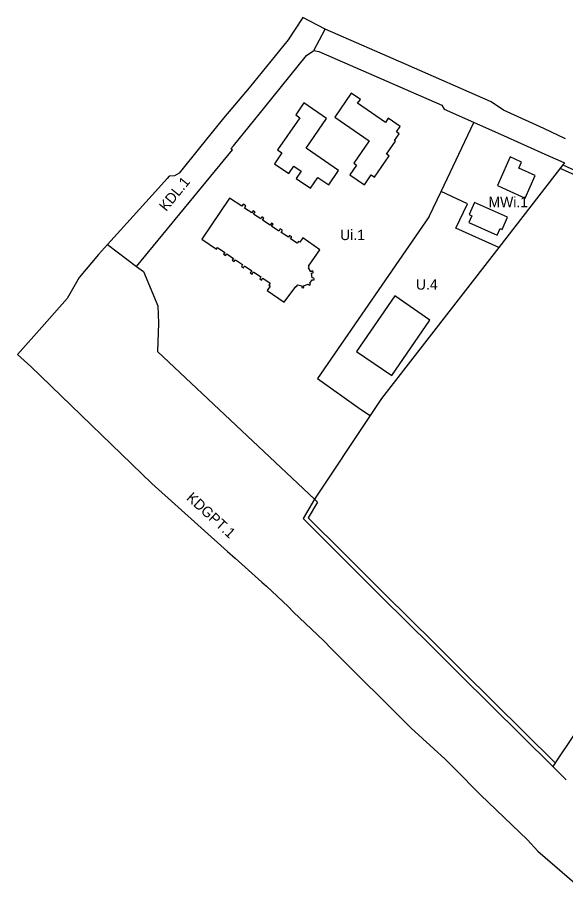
# Model space of a CAD drawing. Extents: x 7427219 to 7428976, y 5542673 to 5543767.
# Drawn here: x 7427399.8 to 7427662.8, y 5542853.3 to 5543277.1 of the extents above; entities that cross this region are included whole.
import ezdxf

# ---------------------------------------------------------------- set-up
doc = ezdxf.new("R2010")
doc.units = 0
for name, color, linetype in [('linie rozgraniczające', 7, 'Continuous'), ('nieprzekraczalne linie zabudowy', 7, 'Continuous'), ('obowiazujace linie zabudowy', 7, 'Continuous'), ('przeznaczenia terenów', 7, 'Continuous')]:
    doc.layers.add(name, color=color, linetype=linetype)

msp = doc.modelspace()

# ---------------------------------------------------------------- linework, layer by layer
at = {"layer": 'linie rozgraniczające'}
for p, q in [((7427615.83, 5543187.62), (7427603.18, 5543193.61)), ((7427597.49, 5543181.6), (7427543.77, 5543103.7))]:
    msp.add_line(p, q, dxfattribs=at)
for points in [[(7427547.42, 5543271.6), (7427536.8, 5543277.12), (7427529.68, 5543266.5), (7427511.02, 5543243.35), (7427498.71, 5543228.81), (7427487.19, 5543214.58), (7427477.35, 5543202.44), (7427475.19, 5543201.11), (7427472.52, 5543200.95), (7427471.58, 5543199.8), (7427467.37, 5543195.09), (7427446.18, 5543171.61), (7427442.97, 5543168.04)], [(7427542.01, 5543261.33), (7427547.42, 5543271.6)], [(7427662.95, 5543218.86), (7427652.55, 5543223.76), (7427633.2, 5543232.59), (7427627.2, 5543236.59), (7427586.32, 5543254.53), (7427547.42, 5543271.6)], [(7427456.96, 5543157.51), (7427503.06, 5543213.5), (7427502.24, 5543214.02), (7427503.46, 5543215.53), (7427518.51, 5543234.15), (7427538.52, 5543258.91), (7427542.01, 5543261.33)], [(7427542.01, 5543261.33), (7427544.42, 5543260.9), (7427603.44, 5543234.99), (7427604.62, 5543233.17), (7427631.67, 5543221.07)], [(7427597.49, 5543181.6), (7427603.18, 5543193.61), (7427618.89, 5543226.79)], [(7427631.67, 5543221.07), (7427654.47, 5543210.87), (7427659.22, 5543208.74), (7427662.41, 5543207.31), (7427661.57, 5543206.3)], [(7427661.57, 5543206.3), (7427630.91, 5543166.64)], [(7427661.57, 5543206.3), (7427676.7, 5543199.54), (7427691.82, 5543192.78), (7427705.68, 5543186.58), (7427719.54, 5543180.39), (7427732.45, 5543174.31), (7427745.35, 5543168.23)], [(7427630.91, 5543166.64), (7427610.27, 5543175.88), (7427615.83, 5543187.62)], [(7427442.97, 5543168.04), (7427438.63, 5543163.23), (7427429.35, 5543152.29), (7427423.66, 5543142.17), (7427411.39, 5543128.32), (7427399.81, 5543115.25), (7427406.08, 5543109.39), (7427464.3, 5543053.23), (7427500.6, 5543020.46), (7427504.23, 5543017.32), (7427517.14, 5543005.76), (7427519.34, 5543003.79), (7427529.74, 5542994.1), (7427532.3, 5542991.42), (7427540.99, 5542983.15), (7427546.83, 5542977.53), (7427550.71, 5542973.49), (7427588.86, 5542935.6), (7427605.09, 5542920.62), (7427609.64, 5542916.28), (7427622.1, 5542903.58), (7427644.62, 5542881.96), (7427649.66, 5542876.48), (7427676.46, 5542853.3)], [(7427442.97, 5543168.04), (7427456.96, 5543157.51)], [(7427630.91, 5543166.64), (7427574.59, 5543094.05), (7427569.09, 5543085.81), (7427542.29, 5543045.63)], [(7427456.96, 5543157.51), (7427460.18, 5543155.09), (7427467.08, 5543138.63), (7427467.4, 5543130.24), (7427467.03, 5543116.62), (7427542.29, 5543045.63)], [(7427543.77, 5543103.7), (7427564.53, 5543088.95), (7427569.09, 5543085.81)], [(7427542.29, 5543045.63), (7427536.85, 5543036.29), (7427554.82, 5543018.4), (7427574.7, 5542998.59), (7427598.52, 5542974.95), (7427612.07, 5542961.53), (7427656.8, 5542917.2)], [(7427729.71, 5543025.77), (7427700.38, 5542982.08), (7427659.59, 5542921.33), (7427656.8, 5542917.2)], [(7427656.8, 5542917.2), (7427663.24, 5542910.82)]]:
    msp.add_lwpolyline(points, dxfattribs=at)
at = {"layer": 'nieprzekraczalne linie zabudowy'}
for p, q in [((7427580.87, 5543143.42), (7427562.5, 5543116.7)), ((7427597.8, 5543131.78), (7427580.87, 5543143.42)), ((7427579.43, 5543105.06), (7427597.8, 5543131.78)), ((7427562.5, 5543116.7), (7427579.43, 5543105.06))]:
    msp.add_line(p, q, dxfattribs=at)
for points in [[(7427744.49, 5543166.43), (7427718.71, 5543178.57), (7427660.31, 5543204.67)], [(7427542.29, 5543045.63), (7427543.78, 5543044.22), (7427539.36, 5543036.62), (7427556.23, 5543019.82), (7427576.11, 5543000.01), (7427599.92, 5542976.37), (7427613.48, 5542962.95), (7427657.94, 5542918.89)]]:
    msp.add_lwpolyline(points, dxfattribs=at)
at = {"layer": 'obowiazujace linie zabudowy'}
for points in [[(7427566.3, 5543196.78), (7427569.54, 5543201.53), (7427571.19, 5543200.4), (7427578.25, 5543210.72), (7427577.01, 5543211.56), (7427581.21, 5543217.71), (7427580.8, 5543217.99), (7427583.09, 5543221.33), (7427581.81, 5543222.21), (7427583.56, 5543224.76), (7427577.77, 5543228.73), (7427576.44, 5543226.79), (7427563.08, 5543235.95), (7427564.38, 5543237.85), (7427560.03, 5543240.83), (7427552.11, 5543229.25), (7427568.65, 5543217.95), (7427561.26, 5543207.13), (7427562.54, 5543206.26), (7427559.32, 5543201.55)], [(7427540.42, 5543195.1), (7427544.01, 5543200.3), (7427549.17, 5543196.75), (7427553.95, 5543203.71), (7427538.38, 5543214.43), (7427548.17, 5543228.71), (7427537.27, 5543236.15), (7427533.33, 5543230.39), (7427535.38, 5543228.97), (7427524.63, 5543213.52), (7427526.72, 5543212.09), (7427523.16, 5543206.91), (7427530.09, 5543202.23), (7427532.4, 5543205.66), (7427535.93, 5543203.27), (7427533.59, 5543199.79)], [(7427545, 5543165.49), (7427536.7, 5543171.26), (7427535.27, 5543169.12), (7427534.65, 5543169.53), (7427534.1, 5543168.7), (7427530.85, 5543170.86), (7427531.45, 5543171.76), (7427530.43, 5543172.43), (7427529.84, 5543171.54), (7427526.28, 5543173.9), (7427526.98, 5543174.96), (7427525.94, 5543175.65), (7427525.22, 5543174.56), (7427521.79, 5543176.84), (7427522.45, 5543177.83), (7427521.71, 5543178.32), (7427521.04, 5543177.31), (7427517.37, 5543179.75), (7427518.02, 5543180.74), (7427517.1, 5543181.35), (7427516.52, 5543180.46), (7427513.14, 5543182.71), (7427513.81, 5543183.72), (7427512.92, 5543184.31), (7427512.22, 5543183.26), (7427508.69, 5543185.61), (7427509.34, 5543186.58), (7427508.03, 5543187.44), (7427507.41, 5543186.52), (7427501.62, 5543190.38), (7427488.27, 5543170.64), (7427495.23, 5543165.8), (7427495.77, 5543166.59), (7427499.25, 5543164.21), (7427498.67, 5543163.36), (7427499.61, 5543162.72), (7427500.21, 5543163.6), (7427503.45, 5543161.38), (7427502.85, 5543160.49), (7427503.76, 5543159.87), (7427504.38, 5543160.77), (7427507.86, 5543158.39), (7427507.25, 5543157.49), (7427508.19, 5543156.85), (7427508.82, 5543157.76), (7427512.19, 5543155.45), (7427511.51, 5543154.46), (7427512.42, 5543153.83), (7427513.14, 5543154.89), (7427516.67, 5543152.47), (7427516.04, 5543151.54), (7427516.98, 5543150.89), (7427517.62, 5543151.82), (7427521.06, 5543149.46), (7427520.41, 5543148.51), (7427521.03, 5543148.09), (7427519.59, 5543145.98), (7427527.81, 5543140.36), (7427533.34, 5543147.94), (7427533.77, 5543147.86), (7427534.32, 5543148.7), (7427536.29, 5543148.23), (7427536.35, 5543147.35), (7427536.84, 5543147.27), (7427537.29, 5543147.45), (7427537.16, 5543148.23), (7427539.38, 5543148.94), (7427539.68, 5543148.62), (7427540.2, 5543148.58), (7427540.38, 5543149.04), (7427540.17, 5543149.42), (7427541.24, 5543151.09), (7427542.02, 5543151.03), (7427542.37, 5543151.24), (7427542.05, 5543151.96), (7427541.23, 5543152.02), (7427540.98, 5543154.25), (7427541.75, 5543154.48), (7427541.8, 5543154.94), (7427541.45, 5543155.35), (7427540.56, 5543154.98), (7427539.48, 5543156.79), (7427539.78, 5543157.36), (7427539.47, 5543157.7)], [(7427619.23, 5543188.31), (7427616.59, 5543182.42), (7427617.87, 5543181.85), (7427616.41, 5543178.6), (7427630.02, 5543172.51), (7427631.48, 5543175.76), (7427632.48, 5543175.31), (7427635.12, 5543181.2)]]:
    msp.add_lwpolyline(points, close=True, dxfattribs=at)
for points in [[(7427641.73, 5543207.61), (7427636.39, 5543210.16), (7427635.1, 5543207.31), (7427630.2, 5543196.41), (7427634.44, 5543194.47), (7427643.54, 5543190.31), (7427648.33, 5543201.2)], [(7427648.33, 5543201.2), (7427640.52, 5543204.8), (7427641.73, 5543207.61)]]:
    msp.add_lwpolyline(points, dxfattribs=at)

# ---------------------------------------------------------------- texts
at = {"layer": 'przeznaczenia terenów'}
for s, rotation, p in [('KDL.1', 50.7206, (7427471.15, 5543183.67)), ('KDGPT.1', 317.4956, (7427480.5, 5543045.77))]:
    msp.add_text(s, height=5, rotation=rotation, dxfattribs=at).set_placement(p)
for s, p in [('MWi.1', (7427625.94, 5543185.99)), ('Ui.1', (7427554.67, 5543170.19)), ('U.4', (7427591.07, 5543146.37))]:
    msp.add_text(s, height=5, dxfattribs=at).set_placement(p)

doc.saveas('drawing.dxf')
